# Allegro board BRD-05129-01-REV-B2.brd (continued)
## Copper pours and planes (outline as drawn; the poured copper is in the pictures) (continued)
(no net) on BOTTOM: 102.07,59.7 102.07,56.73 101.77,56.43 98.98,56.43 98.88,56.54 98.88,59.73 99.01,59.86 101.92,59.86
(no net) on BOTTOM: 101.37,83.5 100.63,84.24 100.63,85.06 100.72,85.15 101.02,85.15 101.3,84.87 101.3,84.5 101.8,84 101.8,83.94
(no net) on BOTTOM: 68.31,78.14 65.05,78.14 64.8,77.88 64.8,77.12 64.67,76.99 64.67,75.87 65.33,75.87 65.37,75.87 65.42,75.85 65.94,75.85 66.32,75.47 68.42,75.47 68.55,75.6 68.55,77.9
(no net) on BOTTOM: 26.61,83.81 27.65,83.81 28.62,84.78 28.62,87.42 28.3,87.75 26.48,87.75 26.46,87.72 26.46,83.96
(no net) on BOTTOM: 107.26,34.56 107.26,35.15 108.81,35.15 109.47,34.49 109.47,33.32 109.37,33.21 108.95,33.21 108.8,33.37 108.8,34.08 108.51,34.37 107.46,34.37
(no net) on BOTTOM: 26.66,83.29 27.87,83.29 27.99,83.17 27.99,81.34 27.7,81.05 27.7,79.22 27.48,79.01 26.63,79.01 26.51,78.89 26.51,77.61 26.56,77.56 29.18,77.56 29.45,77.83 29.45,83.53 29.22,83.76 28.01,83.76 27.77,83.52 26.66,83.52
(no net) on BOTTOM: 91.3,86.55 90.82,86.55 90.78,86.51 90.78,83.3 90.85,83.23 91.44,83.23 91.62,83.4 91.62,84.02 91.96,84.36 92.59,84.36 92.79,84.56 92.79,85.01 92.58,85.22 91.43,85.22 91.38,85.28 91.38,86.47
(no net) on BOTTOM: 5.18,54.22 4.97,54.22 4.92,54.17 4.92,52.47 4.72,52.27 4.11,52.27 4.01,52.17 4.01,49.02 6.65,49.02 6.78,49.14 6.78,52.09 6.63,52.24 5.61,52.24 5.25,52.6 5.25,54.15
(no net) on BOTTOM: 123.22,73.57 124.29,73.57 124.75,73.11 126.17,73.11 126.19,73.13 126.19,75.85 125.99,76.06 123.32,76.06 122.82,75.55 122.82,73.97
(no net) on BOTTOM: 123.49,5 129.26,5 130.6,6.35 130.6,17.59 130.1,18.09 125.91,18.09 125.37,17.55 125.37,12.21 122.98,9.83 122.98,5.51
(no net) on BOTTOM: 70.7,38.31 72.33,38.31 72.59,38.06 72.59,36.52 72.47,36.41 70.97,36.41 70.68,36.69 70.68,37.12 70.7,37.17 70.7,37.22
(no net) on BOTTOM: 62.76,77.63 62.76,76.23 62.64,76.11 62.64,73.27 63.87,72.04 66.78,72.04 66.96,72.22 66.96,73.7 66.84,73.82 64.67,73.82 64.42,74.07 64.42,77.63 64.29,77.76 62.89,77.76
(no net) on BOTTOM: 112.21,93.6 112.21,90.25 112.37,90.09 114.53,90.09 114.68,90.24 114.68,91.43 114.43,91.68 113.46,91.68 113.14,92 113.14,93.61 113.04,93.72 112.33,93.72
(no net) on BOTTOM: 36.19,82.19 36.19,81.15 37.15,80.18 39.8,80.18 40.12,80.51 40.12,82.32 40.1,82.35 36.34,82.35
(no net) on BOTTOM: 22.9,86.35 24.3,87.75 25.85,87.75 25.87,87.72 25.87,85.59 25.52,85.23 24.33,85.23 24.2,85.11 24.2,83.66 24.35,83.51 25.65,83.51 25.67,83.48 25.67,83 25.54,82.87 24.4,82.87 24.27,82.74 24.27,80.19 24.64,79.83 25.85,79.83 25.87,79.8 25.87,77.68 25.81,77.62 23.48,77.62 22.9,78.2
(no net) on BOTTOM: 2.82,72.44 4.38,72.44 4.43,72.39 4.43,70.8 4.59,70.64 4.59,69.45 4.4,69.26 2.82,69.26 2.64,69.43 2.64,70.83 2.77,70.95 2.77,72.39
(no net) on BOTTOM: 117.52,5.08 117.52,11.82 116.91,12.43 113.27,12.43 112.11,11.27 112.11,4.57 112.57,4.11 116.56,4.11
(no net) on BOTTOM: 70.91,55.02 72.54,55.02 72.79,54.76 72.79,53.23 72.68,53.11 71.18,53.11 70.89,53.4 70.89,53.82 70.91,53.88 70.91,53.93
(no net) on BOTTOM: 58.71,50.65 58.71,49.43 58.13,48.84 56.59,48.84 56.44,48.99 56.44,50.28 56.81,50.65
(no net) on BOTTOM: 102.07,42.81 102.07,39.84 101.77,39.54 98.98,39.54 98.85,39.67 98.85,42.81 99.01,42.97 101.92,42.97
(no net) on BOTTOM: 18.86,28.69 18.73,28.56 18.73,27.67 19.24,27.04 19.24,26.66 21.02,24.88 27.14,24.88 27.25,24.99 27.25,28.09 26.65,28.69
(no net) on BOTTOM: 58.63,58.8 58.71,58.72 58.71,57.61 58.55,57.44 56.52,57.44 56.38,57.58 56.38,58.57 56.38,58.57 56.51,58.7 57.04,58.7 57.15,58.8
(no net) on BOTTOM: 104.35,70.06 104.64,69.76 104.64,68.56 103.44,67.36 98.22,67.36 98.12,67.45 98.12,69.52 98.66,70.06
(no net) on BOTTOM: 98.85,35.35 98.85,37.77 98.98,37.89 101.14,37.89 101.53,37.5 103.62,37.5 105.15,35.98 105.15,34.78 105.02,34.65 102.4,34.65 101.88,35.16 99.04,35.16
(no net) on BOTTOM: 106.3,51.95 106.87,51.95 106.87,50.36 106.75,50.24 106.35,50.24 106.21,50.39 106.21,51.86
(no net) on BOTTOM: 38.72,85.9 40.12,84.5 40.12,82.96 40.1,82.93 37.96,82.93 37.61,83.29 37.61,84.48 37.48,84.61 36.03,84.61 35.88,84.45 35.88,83.16 35.86,83.13 35.37,83.13 35.25,83.26 35.25,84.4 35.12,84.53 32.57,84.53 32.2,84.17 32.2,82.95 32.18,82.93 30.05,82.93 29.99,82.99 29.99,85.32 30.57,85.9
(no net) on BOTTOM: 106.36,68.85 106.36,67.25 106.24,67.13 105.85,67.13 105.7,67.28 105.7,68.75 105.79,68.85
(no net) on BOTTOM: 74.3,19.39 77.75,19.39 77.95,19.19 77.95,16.98 77.8,16.83 75.68,16.83 75.3,17.21 74.86,17.21 74.78,17.26 74.69,17.28 74.03,17.28 74.03,18.36 74.16,18.48 74.16,19.25
(no net) on BOTTOM: 56.41,64.36 58.42,64.36 58.71,64.06 58.71,63.03 57.18,63.03 57.07,63.14 56.35,63.14 56.3,63.19 56.3,64.25
(no net) on BOTTOM: 101.27,71.42 96.82,71.42 96.57,71.67 96.57,73.71 96.95,74.09 101.57,74.09 101.7,73.96 101.7,71.85
(no net) on BOTTOM: 124.2,17.79 124.2,12.75 122.47,11.02 122.47,5.38 122.09,5 118.54,5 118.03,5.51 118.03,16.35 119.65,17.97 124.02,17.97
(no net) on BOTTOM: 70.9,47.15 72.54,47.15 72.79,46.89 72.79,45.36 72.68,45.24 71.18,45.24 70.89,45.53 70.89,47.14
(no net) on BOTTOM: 56.46,34.77 56.88,34.77 56.96,34.69 56.96,34.62 56.97,34.56 56.99,34.49 56.99,34.45 57.06,34.37 57.08,34.37 57.1,34.37 57.18,34.33 57.26,34.32 58.71,34.32 58.71,33.09 58.56,32.94 56.54,32.94 56.29,33.19 56.29,34.6
(no net) on BOTTOM: 5.56,42.66 5.49,42.59 5.49,40.25 5.36,40.12 4.6,40.12 4.47,40.25 4.47,44.11 4.78,44.42 7.78,44.44 7.9,44.31 9.84,44.31 10.11,44.05 10.11,42.93 9.83,42.66
BRK_CTL_CONN on TOP (solid shape): 117.88,12.04 117.8,11.96 113.1,11.96 113.03,12.04 113.03,12.19 113.15,12.31 113.15,12.87 113.43,13.15 117.88,13.15
BRK_CTL_CONN on TOP (solid shape): 118.31,16.96 118.31,11.55 117.7,10.94 117.7,5.25 116.56,4.11 112.57,4.11 112.11,4.57 112.11,8.3 113.5,8.3 113.5,6 113.5,5.97 113.51,5.91 113.52,5.85 113.54,5.8 113.57,5.74 113.61,5.69 113.65,5.65 113.69,5.6 113.74,5.57 113.8,5.54 113.86,5.52 113.91,5.5 113.98,5.5 114.01,5.5 116.31,5.5 116.34,5.5 116.4,5.5 116.46,5.52 116.52,5.54 116.57,5.57 116.62,5.6 116.67,5.65 116.71,5.69 116.74,5.74 116.77,5.8 116.79,5.85 116.81,5.91 116.81,5.97 116.81,6 116.81,8.3 116.81,8.34 116.81,8.4 116.79,8.46 116.77,8.51 116.74,8.57 116.71,8.62 116.67,8.66 116.62,8.7 116.57,8.74 116.52,8.77 116.46,8.79 116.4,8.8 116.34,8.81 116.31,8.81 114.01,8.81 113.98,8.81 113.91,8.8 113.86,8.79 113.8,8.77 113.74,8.74 113.69,8.7 113.65,8.66 113.61,8.62 113.57,8.57 113.54,8.51 113.52,8.46 113.51,8.4 113.5,8.34 113.5,8.3 112.11,8.3 112.11,11.27 113.05,12.22 117.23,12.22 117.23,12.67 113.15,12.67 113.15,16.86 113.46,17.17 118.11,17.17
BRK_CTL_CONN on BOTTOM (solid shape): 117.52,11.82 117.52,5.08 116.56,4.11 112.57,4.11 112.11,4.57 112.11,8.3 113.5,8.3 113.5,6 113.5,5.97 113.51,5.91 113.52,5.85 113.54,5.8 113.57,5.74 113.61,5.69 113.65,5.65 113.69,5.6 113.74,5.57 113.8,5.54 113.86,5.52 113.91,5.5 113.98,5.5 114.01,5.5 116.31,5.5 116.34,5.5 116.4,5.5 116.46,5.52 116.52,5.54 116.57,5.57 116.62,5.6 116.67,5.65 116.71,5.69 116.74,5.74 116.77,5.8 116.79,5.85 116.81,5.91 116.81,5.97 116.81,6 116.81,8.3 116.81,8.34 116.81,8.4 116.79,8.46 116.77,8.51 116.74,8.57 116.71,8.62 116.67,8.66 116.62,8.7 116.57,8.74 116.52,8.77 116.46,8.79 116.4,8.8 116.34,8.81 116.31,8.81 114.01,8.81 113.98,8.81 113.91,8.8 113.86,8.79 113.8,8.77 113.74,8.74 113.69,8.7 113.65,8.66 113.61,8.62 113.57,8.57 113.54,8.51 113.52,8.46 113.51,8.4 113.5,8.34 113.5,8.3 112.11,8.3 112.11,11.27 113.27,12.43 116.91,12.43
DC_LINK on TOP (solid shape): 110.77,62.28 106.73,62.28 106.73,65.07 108.35,66.7 110.77,66.7
DC_LINK on TOP (solid shape): 111.58,45.23 107.72,45.23 107.72,48.66 108.86,49.81 111.58,49.81
DC_LINK on TOP (solid shape): 112.42,28.37 108.11,28.37 108.11,31.42 107.64,31.42 107.57,31.49 107.57,31.62 108.86,32.91 112.42,32.91
DC_LINK on BOTTOM (solid shape): outline of 103 points within 122.98,5 130.6,18.09
DC_LINK on TOP: outline of 81 points within 93.01,20.75 113.36,66.7
DC_LINK on TOP: 124.51,4.36 128.62,4.36 130.6,6.35 130.6,17.61 130.39,17.83 126.44,17.83 126.44,13.28 123.29,10.13 123.29,5.58
DC_LINK on BOTTOM: 106.47,61.77 99.97,61.77 98.45,60.24 98.45,49.22 99.13,48.54 106.52,48.54 106.52,44.93 102.71,44.93 101.34,43.56 98.9,43.56 98.34,43 98.34,35.17 99.53,33.98 103.24,33.98 104.74,32.48 114.73,32.48 114.73,29 109.77,29 109.52,28.75 109.52,24.81 107.84,23.13 98.62,23.13 96.11,20.62 93.06,20.62 93.01,20.67 93.01,27.35 94.79,29.13 94.79,64.31 95.17,64.69 95.17,65.88 96.14,66.85 106.69,66.85 106.69,61.98
DC_LINK on L03_SIG: 138.48,19.99 138.48,4.36 135.53,1.42 108.99,1.42 108.99,11.24 108.08,12.16 105.98,12.16 104.96,13.17 104.96,14.43 102.89,16.51 88.62,16.51 88.18,16.94 88.18,25.83 90.6,28.24 90.6,64.92 92.4,66.72 104.9,66.72 106.42,65.2 106.42,34.87 107.87,33.42 122.3,33.42 122.3,19.99 ; 1 cut-out
DC_LINK on L07_PWR: 138.73,3.53 136.48,1.28 88.18,1.28 88.18,25.83 90.22,27.86 90.22,64.54 91.11,65.43 138.73,65.43 ; 2 cut-outs
DCLINK_CONN on TOP: 120.39,22.08 120.39,24.71 121.02,25.33 121.02,27.58 122.6,29.16 128.62,29.16 128.98,28.8 128.98,19.14 128.46,18.63 121.89,18.63 121.12,19.4 121.12,21.35
DCLINK_CONN on BOTTOM: 120.39,26.96 122.42,28.98 128.51,28.98 128.98,28.52 128.98,19.14 128.46,18.63 120.83,18.63 120.39,19.07
DCLINK_INPUT on TOP: 118.97,24.86 118.97,22.35 118.89,22.27 118.03,22.27 117.65,21.89 117.65,18.08 117.27,17.7 113.48,17.7 112.7,18.49 112.7,25.6 113.05,25.95 117.9,25.95 118.21,25.65 118.21,25.22 118.31,25.12 118.72,25.12
DCLINK_INPUT on BOTTOM: 113.48,17.7 112.82,18.36 112.82,24.05 119.79,24.05 119.79,18.96 118.53,17.7
DCLINK_VOCM2 on BOTTOM (solid shape): 72.59,38.06 72.59,36.52 72.47,36.41 70.97,36.41 70.68,36.69 70.68,37.12 70.7,37.17 70.7,37.22 70.7,38.31 72.33,38.31
GEM0_AVDD_3V3 on TOP: 68.41,97.92 69.37,97.92 69.39,97.9 69.39,95.72 69.3,95.63 66.92,95.63 66.16,96.38 65.69,96.38 65.66,96.41 65.66,97.15 68.04,97.15 68.12,97.15 68.35,97.38 68.35,97.86
GEM0_AVDD_3V3 on L03_SIG: 69.39,95.68 69.39,96.78 68.97,97.19 65.64,97.19 65.07,96.62 60.24,96.62 59.86,96.24 59.86,95.65 60.93,94.59 67.17,94.59 68.01,95.42 69.13,95.42
GEM1_AVDD_3V3 on BOTTOM: 107.36,90.09 107.36,89.2 107.74,88.82 107.74,87.17 107.36,86.79 106.09,86.79 105.71,87.17 105.71,89.96 105.84,90.09
GEM1_AVDD_3V3 on L10_SIG: 106.6,89.58 106.6,87.02 106.37,86.79 105.69,86.79 105.36,87.12 98.57,87.12 98.12,87.57 93.04,87.57 92.23,88.38 92.23,90.25 92.36,90.38 93.38,90.38 93.48,90.29 93.48,89.56 93.91,89.12 99.48,89.12 100.06,89.7 100.06,90.33 100.28,90.55 100.88,90.55 101.93,89.51 105.23,89.51 105.48,89.76 106.42,89.76
GEM2_AVDD_3V3 on TOP: 107.36,92.98 105.67,92.98 105.44,92.75 105.44,90.36 105.71,90.09 107.36,90.09
GEM2_AVDD_3V3 on L10_SIG: 93.85,89.81 93.85,92.04 94.48,92.68 97.53,92.68 97.96,93.11 106.35,93.11 106.83,92.63 106.83,90.93 106.12,90.22 103.04,90.22 102.18,91.08 99.95,91.08 99.68,90.81 99.68,89.88 99.45,89.66 94,89.66
GISOIN_RS485 on TOP (solid shape): 111.59,80.44 111.59,79.12 111.45,78.98 110.28,78.98 110.05,79.21 110.05,80.31 110.27,80.53 111.51,80.53
GISOIN_RS485 on TOP (solid shape): 115.68,86.78 115.68,85.48 116.83,84.33 116.83,82.65 116.8,82.62 115.05,82.62 114.97,82.69 114.97,84.41 114.35,85.03 114.35,86.87 114.5,87.01 115.44,87.01
GISOIN_RS485 on L05_SIG: 125.32,100.22 127.3,100.22 128.06,99.46 128.06,87.17 123.82,82.93 115.39,82.93 111.5,79.04 109.75,79.04 109.34,79.45 109.34,83.87 113.61,88.13 121.94,88.13 124.08,90.27 124.08,98.98
MOTOR_PA_HS on TOP (solid shape): 114.19,40.88 114.14,40.89 114.09,40.89 114.02,40.89 113.94,40.87 113.94,39.89 114.02,39.88 114.09,39.87 114.14,39.87 114.19,39.88 114.19,37.94 111.07,37.94 111.07,42.19 114.19,42.19
MOTOR_PA_HS on TOP: 114.32,47.32 123.08,47.32 123.08,39.09 122.02,39.09 122.02,37.51 123.08,37.51 123.08,35.5 121.64,34.06 113.94,34.06 113.92,34.03 110.13,34.03 110.13,35.38 109.57,35.94 108.94,35.94 108.71,36.17 108.71,36.77 108.84,36.9 108.84,39.8 108.78,39.85 108.78,41.85 108.94,42.01 113.61,42.01 114.12,42.52 114.12,47.11
MOTOR_PA_HS on L03_SIG: 123.08,35.5 121.64,34.06 113.94,34.06 113.92,34.03 110.13,34.03 110.13,35.38 109.57,35.94 108.94,35.94 108.71,36.17 108.71,36.77 108.84,36.9 108.84,39.8 108.78,39.85 108.78,41.85 108.94,42.01 113.61,42.01 114.12,42.52 114.12,47.11 114.32,47.32 123.08,47.32 ; 1 cut-out
MOTOR_PA_OUT on TOP: 137.93,40.56 137.93,47.67 123.82,47.67 123.82,39.19 126.06,39.19 126.54,39.67 137.04,39.67
MOTOR_PA_OUT on L03_SIG: 137.93,40.56 137.93,47.67 123.82,47.67 123.82,39.19 126.06,39.19 126.54,39.67 137.04,39.67 ; 1 cut-out
MOTOR_PA_VOCM2 on BOTTOM (solid shape): 72.79,46.89 72.79,45.36 72.68,45.24 71.18,45.24 70.89,45.53 70.89,45.95 70.91,46 70.91,46.05 70.91,47.15 72.54,47.15
MOTOR_PB_HS on TOP (solid shape): 114.19,54.83 110.77,54.83 110.77,59 114.19,59
MOTOR_PB_HS on TOP: 123.08,47.93 114.22,47.93 114.07,48.08 114.07,50.52 113.89,50.69 110.16,50.69 110.13,50.72 110.13,52.22 109.67,52.68 108.91,52.68 108.71,52.88 108.71,54.12 108.86,54.28 108.86,59 114.27,59 114.91,58.36 123.08,58.36
MOTOR_PB_HS on L03_SIG: 123.08,47.93 114.22,47.93 114.07,48.08 114.07,50.52 113.89,50.69 110.16,50.69 110.13,50.72 110.13,52.22 109.67,52.68 108.91,52.68 108.71,52.88 108.71,54.12 108.86,54.28 108.86,59 114.27,59 114.91,58.36 123.08,58.36 ; 1 cut-out
MOTOR_PB_OUT on TOP: 137.88,48.33 137.88,54.28 135.86,54.28 135.12,53.54 131.44,53.54 130.7,54.28 124.3,54.28 123.95,53.92 123.95,48.79 124.41,48.33
MOTOR_PB_OUT on L03_SIG: 137.88,48.33 137.88,54.28 135.86,54.28 135.12,53.54 131.44,53.54 130.7,54.28 124.3,54.28 123.95,53.92 123.95,48.79 124.41,48.33 ; 1 cut-out
MOTOR_PB_VOCM2 on BOTTOM (solid shape): 72.79,54.76 72.79,53.23 72.68,53.11 71.18,53.11 70.89,53.4 70.89,53.82 70.91,53.87 70.91,53.93 70.91,55.02 72.54,55.02
MOTOR_PC_HS on TOP (solid shape): 113.69,71.73 110.41,71.73 110.41,75.93 113.69,75.93
MOTOR_PC_HS on TOP, L03_SIG: 107.82,71.37 107.82,69.92 108.15,69.59 109.19,69.59 109.6,69.19 109.6,67.76 109.77,67.59 113.46,67.59 114.09,66.95 114.09,60.63 115.44,59.28 122.78,59.28 123.08,59.58 123.08,65.5 123.06,65.53 123.06,67.15 122.21,68 120.58,68 119.3,69.29 119.3,75.46 118.83,75.93 108.37,75.93 108.37,71.92
MOTOR_PC_OUT on TOP: 124.1,64.03 137.84,64.03 137.84,55.04 135.23,55.04 134.41,54.22 131.8,54.22 130.98,55.04 124.33,55.04 124.1,55.27
MOTOR_PC_OUT on L03_SIG: 124.1,64.03 137.84,64.03 137.84,55.04 135.23,55.04 134.41,54.22 131.8,54.22 130.98,55.04 124.33,55.04 124.1,55.27 ; 1 cut-out
MOTOR_PC_VOCM2 on BOTTOM (solid shape): 72.79,62.19 72.79,60.65 72.68,60.54 71.18,60.54 70.89,60.82 70.89,61.25 70.91,61.3 70.91,61.35 70.91,62.44 72.54,62.44
PA_HB on TOP (solid shape): 101.52,33.83 102.15,33.2 105.2,33.2 105.2,32.48 98.62,32.48 98.62,37.51 101.52,37.51
PA_HO on BOTTOM (solid shape): 106.87,33.47 106.75,33.35 106.35,33.35 106.21,33.5 106.21,34.97 106.3,35.06 106.87,35.06
PA_HOG on BOTTOM (solid shape): 109.47,34.49 109.47,33.32 109.37,33.21 108.95,33.21 108.8,33.37 108.8,34.08 108.51,34.37 107.46,34.37 107.26,34.56 107.26,35.15 108.81,35.15
PA_LO on TOP (solid shape): 106.67,44.55 106.67,43.77 106.61,43.71 105.78,43.71 105.33,43.26 105.33,40.77 105.29,40.7 105.22,40.67 105.2,40.67 104.83,40.31 105.2,39.94 105.35,39.97 105.47,40.05 105.54,40.08 105.61,40.05 105.7,39.97 105.7,38.55 105.28,38.55 105.17,38.67 105.17,39.07 104.24,40 104.24,42.34 104.52,42.62 104.52,43.81 105.36,44.65 106.57,44.65
PA_LOG on TOP (solid shape): 109.57,44.71 109.57,43.29 108.64,43.29 108.26,43.67 107.16,43.67 107.08,43.75 107.08,44.63 107.34,44.88 109.4,44.88
PB_HB on TOP (solid shape): 101.77,54.02 101.77,50.47 101.88,50.36 104.8,50.36 105.03,50.14 105.03,49.2 104.77,48.94 98.88,48.94 98.62,49.2 98.62,49.42 99.27,49.42 99.28,49.37 99.29,49.32 99.31,49.27 99.33,49.22 99.37,49.18 99.4,49.14 99.45,49.11 99.5,49.08 99.55,49.07 99.6,49.06 99.65,49.06 99.71,49.06 99.76,49.08 99.81,49.1 99.85,49.12 99.9,49.16 99.93,49.2 99.96,49.24 99.98,49.29 100,49.34 100.01,49.4 100.01,49.45 100,49.5 99.98,49.56 99.96,49.6 99.93,49.65 99.9,49.69 99.85,49.72 99.81,49.75 99.76,49.77 99.71,49.79 99.65,49.79 99.6,49.79 99.55,49.78 99.5,49.76 99.45,49.74 99.4,49.71 99.37,49.67 99.33,49.63 99.31,49.58 99.29,49.53 99.28,49.48 99.27,49.42 98.62,49.42 98.62,54.4 101.39,54.4
PB_HO on BOTTOM (solid shape): 106.87,50.36 106.75,50.24 106.35,50.24 106.21,50.39 106.21,51.86 106.3,51.95 106.87,51.95
PB_HOG on BOTTOM (solid shape): 109.47,51.38 109.47,50.21 109.37,50.1 108.95,50.1 108.8,50.26 108.8,50.97 108.51,51.26 107.46,51.26 107.26,51.45 107.26,52.04 108.81,52.04
PB_LO on TOP (solid shape): 106.67,60.66 106.61,60.6 105.78,60.6 105.33,60.16 105.33,59.6 105.28,59.59 104.96,59.23 105.28,58.86 105.33,58.86 105.33,57.23 105.7,56.86 105.7,55.44 105.28,55.44 105.17,55.56 105.17,56.47 104.55,57.08 104.55,60.73 105.26,61.44 106.67,61.44
PB_LOG on TOP (solid shape): 109.57,61.61 109.57,60.18 108.64,60.18 108.26,60.56 107.16,60.56 107.08,60.65 107.08,61.52 107.34,61.78 109.4,61.78
PC4_CON_PGND on L10_SIG: 56.77,19.6 56.77,13.51 55.85,12.59 52.6,12.59 48.31,8.3 31.75,8.3 31.09,8.96 31.09,10.54 32.05,11.5 47.06,11.5 50.54,14.98 53.18,14.98 54.15,15.95 54.15,18.69 55.19,19.73 56.64,19.73
PC_HB on TOP (solid shape): 101.07,67.27 101.45,66.9 101.46,66.9 101.47,66.88 101.6,66.79 101.75,66.76 101.91,66.8 102.04,66.9 104.26,66.9 104.38,66.79 104.38,65.98 104.25,65.86 101.88,65.86 101.35,65.32 101.25,65.32 101.18,65.35 101.15,65.43 100.78,65.79 100.42,65.43 100.39,65.35 100.31,65.32 99.79,65.32 99.74,65.33 99.69,65.34 99.65,65.33 99.6,65.32 97.96,65.32 97.44,65.85 97.44,65.88 97.38,66.08 97.23,66.22 97.23,69.67 101.07,69.67
PC_HO on BOTTOM (solid shape): 106.36,67.25 106.24,67.13 105.85,67.13 105.7,67.28 105.7,68.75 105.79,68.85 106.36,68.85
PC_HOG on BOTTOM (solid shape): 108.97,68.27 108.97,67.1 108.86,66.99 108.44,66.99 108.29,67.15 108.29,67.87 108.01,68.15 106.95,68.15 106.75,68.35 106.75,68.93 108.31,68.93
PC_LO on TOP (solid shape): 106.16,78.43 106.16,77.55 106.1,77.5 105.27,77.5 104.82,77.05 104.82,74.12 105.19,73.75 105.19,72.33 104.78,72.33 104.66,72.45 104.66,73.36 104.05,73.97 104.05,77.62 105.03,78.6 105.99,78.6
PC_LOG on TOP (solid shape): 109.06,78.5 109.06,77.07 108.14,77.07 107.75,77.45 106.65,77.45 106.57,77.54 106.57,78.41 106.83,78.67 108.89,78.67
PL_1V8 on BOTTOM (solid shape): 40.12,82.32 40.12,80.51 39.8,80.18 37.15,80.18 36.19,81.15 36.19,82.19 36.34,82.35 40.1,82.35
PL_1V8 on TOP: 12.8,42.34 11.22,42.34 10.38,41.5 10.38,38.1 10.92,37.56 14.65,37.56 21.45,30.77 27.9,30.77 27.91,30.76 40.69,30.76 43.2,33.27 43.2,35.84 45.51,38.15 48.43,38.15 53.64,43.35 53.64,46.66 51.1,49.2 51.1,55.67 50.59,56.18 46.27,56.18 38.65,48.56 38.65,40.56 36.5,38.4 20.7,38.4 18.41,40.69 13.69,40.69 12.85,41.52 12.85,42.29
PL_1V8 on TOP: 69.11,79.95 69.11,76.42 66.29,73.6 61.11,73.6 60.63,74.09 58.19,74.09 57.55,73.45 51.08,73.45 50.57,72.94 33.45,72.94 32.48,73.91 32.48,84.93 33.22,85.67 41.04,85.67 43.99,82.72 52.62,82.72 55.72,79.62 62.05,79.62 62.61,80.18 65.96,80.18 65.96,79.17 66.21,78.91 67.23,78.91 67.61,79.29 67.61,80.18 67.86,80.44 68.63,80.44
PL_1V8 on L03_SIG: 85.98,17.88 85.98,26.21 64.41,47.77 52.22,47.77 50.95,46.5 50.95,43.63 53.36,41.22 55.04,41.22 78.69,17.57 85.67,17.57
PL_1V8 on L07_PWR: 105.05,89.84 105.05,78.96 103.48,77.39 83.28,77.39 64.66,58.77 64.66,41.07 61.85,38.25 39.57,38.25 39.01,38.81 39.01,43.05 39.43,43.47 47,43.47 48.71,45.18 48.71,56.13 51.48,58.9 51.48,69.06 61.54,79.12 61.54,84.3 66.85,84.3 71.01,88.46 71.01,92.32 102.56,92.32
PL_2V5 on BOTTOM (solid shape): 58.71,49.43 58.13,48.84 56.59,48.84 56.44,48.99 56.44,50.28 56.81,50.65 58.71,50.65
PL_2V5 on BOTTOM (solid shape): 58.71,58.72 58.71,57.61 58.55,57.44 56.52,57.44 56.38,57.58 56.38,58.56 56.51,58.7 57.04,58.7 57.15,58.8 58.63,58.8
PL_2V5 on BOTTOM (solid shape): 56.96,34.64 56.96,34.62 56.97,34.56 56.99,34.49 56.99,34.45 57.06,34.37 57.08,34.37 57.1,34.37 57.18,34.33 57.26,34.32 58.71,34.32 58.71,33.09 58.56,32.94 56.54,32.94 56.29,33.19 56.29,34.6 56.46,34.77 56.83,34.77
PL_2V5 on BOTTOM: 58.67,25.73 54.63,25.73 54.28,26.08 54.28,27.99 54.57,28.28 57.29,28.28 57.67,27.9 58.11,27.9 58.19,27.85 58.28,27.83 58.94,27.83 58.94,26.76 58.81,26.63 58.81,25.87
PL_2V5 on BOTTOM: 58.71,42.48 58.71,41.26 58.13,40.68 56.59,40.68 56.44,40.82 56.44,42.11 56.81,42.48
PL_2V5 on L05_SIG: 55.98,59.97 61.51,59.97 61.9,59.58 61.9,25.34 61.67,25.12 56.18,25.12 54.43,26.87 54.43,28.65 55.8,30.02 55.8,59.79
PL_3V3 on BOTTOM (solid shape): 58.71,55.9 58.71,54.88 56.73,54.88 56.28,55.33 56.28,56.53 56.43,56.68 57.93,56.68
PL_3V3 on BOTTOM (solid shape): 58.71,64.06 58.71,63.03 57.18,63.03 57.07,63.14 56.35,63.14 56.3,63.19 56.3,64.25 56.41,64.36 58.42,64.36
PL_3V3 on BOTTOM (solid shape): 74.38,23.97 71.97,23.97 71.42,23.41 70.32,23.41 69.77,23.97 69.76,23.97 69.23,24.5 69.23,25.54 69.38,25.7 74.38,25.7
PL_3V3 on BOTTOM (solid shape): 58.71,39.56 58.71,38.52 57.26,38.52 57.18,38.51 57.11,38.48 57.07,38.46 56.81,38.19 56.41,38.19 56.28,38.32 56.28,39.73 56.44,39.88 58.39,39.88
PL_3V3 on TOP: 107.9,91.58 107.9,93.55 108.12,93.77 109.52,93.77 109.77,93.52 109.77,91.74 109.61,91.58
PL_3V3 on BOTTOM: 62.87,25.74 61.48,25.74 61.22,25.99 61.22,27.83 61.88,27.83 62.04,27.89 62.13,28.03 62.13,28.04 62.24,28.15 62.24,28.53 62.37,28.66 63.38,28.66 63.51,28.53 63.51,26.38
PL_3V3 on BOTTOM: 75.06,84.02 75.44,84.02 75.57,83.89 75.57,82.87 75.44,82.75 73.28,82.75 72.97,83.06 72.97,85.06 73,85.09 74.78,85.09 74.8,85.07 74.8,84.28
PL_3V3 on BOTTOM: 108.38,88.95 109.65,88.95 110.16,88.44 110.16,86.91 110.03,86.79 108.25,86.79 108.25,88.82
PL_3V3 on BOTTOM: 56.43,48.51 57.93,48.51 58.71,47.73 58.71,46.71 56.73,46.71 56.28,47.16 56.28,48.36
PL_3V3 on L03_SIG: 81.12,72.84 84.58,72.84 85.87,71.55 85.87,42.11 83.71,39.95 75.05,39.95 74.37,40.64 74.37,70.91 75.92,72.46 80.74,72.46
PL_3V3 on L07_PWR: 14.42,53.64 15.06,54.28 35.78,54.28 36.62,53.44 36.62,48.48 33.78,45.64 14.63,45.64 14.42,45.84
PL_3V3 on L08_PWR: 73.02,116.45 83.54,116.45 83.54,117.72 86.65,117.72 86.65,117.21 87.25,115.77 88.68,115.18 101.39,115.18 102.83,115.77 103.42,117.21 103.42,117.72 135.05,117.71 137.65,116.63 138.73,114.03 138.73,4.96 137.66,2.36 135.05,1.28 4.95,1.27 2.35,2.35 1.27,4.95 1.27,16 28.32,16 29.03,16.71 29.03,19.02 47.67,19.02 50.77,22.12 50.77,27.66 49.04,29.38 44.29,29.38 40.81,32.86 40.81,43.48 35.94,48.36 35.94,53.41 39.62,57.09 39.62,67.18 42.24,69.79 44.7,69.79 44.73,69.82 45.34,69.82 45.37,69.86 46.49,69.86 49.91,73.27 63.17,73.27 73.02,83.13
PL_4V5_TRQ on TOP (solid shape): 93.48,15.86 93.48,15.01 93.23,14.75 90.1,14.75 89.84,15.01 89.84,15.86 90.1,16.12 93.23,16.12
PL_4V5_TRQ on BOTTOM (solid shape): 77.95,19.19 77.95,16.98 77.8,16.83 77.47,16.83 77.47,17.33 77.39,17.51 77.21,17.58 76.7,17.58 76.6,17.56 76.52,17.5 76.45,17.47 76.38,17.5 76.29,17.56 76.2,17.58 75.69,17.58 75.51,17.51 75.43,17.33 75.43,17.21 74.86,17.21 74.78,17.26 74.69,17.28 74.03,17.28 74.03,18.36 74.16,18.48 74.16,19.25 74.3,19.39 77.75,19.39
PL_4V5_TRQ on L10_SIG: 78.18,4.39 92.6,4.39 93.72,5.51 93.72,15.46 92.63,16.56 87.17,16.56 85.98,15.36 79.04,15.36 77.69,16.71 77.69,19.22 77.44,19.48 71.83,19.48 71.24,18.89 71.24,11.32
PL_5V0 on BOTTOM (solid shape): 126.19,75.85 126.19,73.13 126.17,73.11 124.75,73.11 124.29,73.57 124.09,73.57 124.09,74.04 124.01,74.22 123.83,74.29 123.32,74.29 123.14,74.22 123.07,74.04 123.07,73.96 123.01,73.87 122.9,73.89 122.82,73.97 122.82,75.55 123.32,76.06 125.99,76.06
PL_5V0 on L10_SIG: 136.24,68.98 127.2,68.98 121.54,74.65 121.54,89.76 116.95,94.34 116.95,97.65 117.32,98.01 129.71,98.01 130.86,96.87 130.86,92.17 137.82,85.21 137.82,70.56
PL_12V0 on TOP (solid shape): 105.25,69.83 105.25,69.45 105.2,69.37 105.19,69.29 105.19,67.9 101.99,67.9 101.67,68.23 101.67,70.34 104.74,70.34
PL_12V0 on TOP (solid shape): 105.4,53.31 105.41,53.27 105.4,53.24 105.34,53.13 105.32,53.01 105.43,52.75 105.69,52.64 105.7,52.64 105.74,52.62 105.76,52.59 105.76,52.56 105.75,52.55 105.71,52.48 105.7,52.39 105.7,51.01 102.5,51.01 102.18,51.33 102.18,53.45 105.25,53.45
PL_12V0 on TOP (solid shape): 105.76,36.25 105.76,35.67 105.74,35.65 105.72,35.61 105.7,35.57 105.7,35.53 105.7,35.5 105.7,34.12 102.5,34.12 102.18,34.44 102.18,35.25 102.36,35.43 102.36,35.99 104.83,35.99 104.84,35.93 104.85,35.88 104.87,35.83 104.9,35.78 104.93,35.74 104.97,35.7 105.01,35.67 105.06,35.65 105.11,35.63 105.16,35.62 105.22,35.62 105.27,35.62 105.32,35.64 105.37,35.66 105.42,35.69 105.46,35.72 105.49,35.76 105.52,35.81 105.55,35.86 105.56,35.91 105.57,35.96 105.57,36.01 105.56,36.07 105.55,36.12 105.52,36.17 105.49,36.21 105.46,36.25 105.42,36.29 105.37,36.32 105.32,36.34 105.27,36.35 105.22,36.36 105.16,36.35 105.11,36.34 105.06,36.33 105.01,36.3 104.97,36.27 104.93,36.23 104.9,36.19 104.87,36.14 104.85,36.09 104.84,36.04 104.83,35.99 102.36,35.99 102.36,36.56 105.45,36.56
PL_12V0 on BOTTOM (solid shape): 101.42,54.25 103.77,54.25 105.15,52.87 105.15,51.67 105.02,51.54 102.4,51.54 101.88,52.05 98.88,52.05 98.88,54.55 99.11,54.78 100.88,54.78
PL_12V0 on BOTTOM (solid shape): 104.64,69.76 104.64,68.56 103.44,67.36 102.04,67.36 101.75,67.5 101.46,67.36 98.22,67.36 98.12,67.45 98.12,69.52 98.66,70.06 104.35,70.06
PL_12V0 on BOTTOM (solid shape): outline of 89 points within 98.85,34.65 105.15,37.89
PL_12V0 on BOTTOM: 78.7,25.23 78.7,23.68 77.97,22.95 77.97,21.52 77.99,21.5 80.71,21.5 80.91,21.7 80.91,25.23
PL_12V0 on L08_PWR: 98,28.2 97,27.2 79.68,27.2 78.56,26.08 78.56,20.8 79.63,19.73 105.13,19.73 107.34,21.94 107.34,68.47 106.3,69.52 99.21,69.52 98,68.31
PL_ETH_0V9 on TOP (solid shape): 102.47,83.41 102.44,83.38 101.56,83.38 101.13,83.81 101.13,84.19 100.63,84.69 100.63,85.07 100.82,85.26 101.03,85.26 101.27,85.51 101.27,86.33 101.49,86.55 102.47,86.55
PL_ETH_0V9 on TOP (solid shape): 92.76,84.88 92.76,84.12 92.55,83.92 91.56,83.92 91.49,83.99 91.49,84.08 91.5,84.09 91.54,84.16 91.55,84.25 91.55,84.76 91.55,84.82 91.52,84.87 91.51,84.9 91.6,85 92.12,85 92.16,85 92.2,85.01 92.63,85.01
PL_ETH_0V9 on BOTTOM (solid shape): 101.3,84.87 101.3,84.5 101.77,84.03 101.75,84 101.72,83.94 101.71,83.87 101.71,83.84 101.37,83.5 100.63,84.24 100.63,85.06 100.67,85.1 101.07,85.1
PL_ETH_0V9 on BOTTOM (solid shape): 91.38,86.47 91.38,85.28 91.43,85.22 92.58,85.22 92.79,85.01 92.79,84.56 92.59,84.36 91.96,84.36 91.62,84.02 91.62,83.4 91.44,83.23 90.85,83.23 90.78,83.3 90.78,86.51 90.82,86.55 91.3,86.55
PL_ETH_0V9 on BOTTOM (solid shape): 75.19,91.53 75.19,90.75 74.7,90.75 74.52,90.68 74.44,90.5 74.44,89.99 74.46,89.89 74.52,89.81 74.55,89.73 74.52,89.66 74.46,89.58 74.44,89.48 74.44,88.97 74.52,88.79 74.7,88.72 74.79,88.72 74.88,88.65 74.86,88.54 74.81,88.49 74.81,88.15 74.76,88.07 74.74,87.98 74.74,87.32 73.67,87.32 73.54,87.45 72.97,87.45 72.97,88.47 72.98,88.52 72.98,88.57 72.98,88.61 72.97,88.66 72.97,89.88 73.33,90.24 73.33,90.64 73.35,90.72 73.36,90.8 73.35,90.87 73.33,90.96 73.33,91.23 73.83,91.74 74.98,91.74
PL_ETH_0V9 on L10_SIG: 102.89,86.61 102.89,80.11 99.35,76.56 92.74,76.56 92.55,76.37 79.93,76.37 74.88,81.43 74.88,83.89 74.21,84.55 74.21,86.95 73.73,87.44 73.73,90.22 75.59,92.07 86.15,92.07 91.39,86.84 92.02,86.84 94.31,84.55 98.24,84.55 98.83,85.14 98.83,86.41 99.03,86.61
PMOD_3V3 on L05_SIG: 6.93,17.9 12.87,17.9 13.66,17.12 13.66,8.68 13.2,8.23 8.33,8.23 6.7,9.85 3.12,9.85 2.49,10.49 2.49,16.1 2.99,16.61 5.63,16.61
PS_1V2 on BOTTOM (solid shape): 28.62,87.42 28.62,84.78 27.65,83.81 26.61,83.81 26.46,83.96 26.46,87.72 26.48,87.75 28.3,87.75
PS_1V2 on L12_SIG: 59.89,96.69 65.99,96.69 69.03,93.65 69.03,92.45 67.66,91.08 67.66,87.73 68.79,86.6 68.79,85.76 67.53,84.5 65.86,84.5 65.83,84.53 62.91,84.53 57.1,78.71 51.71,78.71 50.82,77.82 45.56,77.82 44.67,78.71 33.17,78.71 26.97,84.91 26.97,87.37 27.56,87.96 41.58,87.96 46.12,83.41 49.45,83.41 52.4,86.36 56.87,86.36 58.77,88.26 58.77,93.77 59.29,94.29 59.29,96.1
PS_1V8 on TOP (solid shape): 113.93,96.98 113.93,95.58 113.84,95.49 112.83,95.49 112.64,95.67 112.64,96.91 112.88,97.15 113.76,97.15
PS_1V8 on BOTTOM (solid shape): 59.59,78.37 59.59,76.37 59.34,76.12 59.23,76.12 59.23,76.64 59.16,76.82 58.98,76.89 58.47,76.89 58.37,76.87 58.29,76.82 58.21,76.79 58.14,76.82 58.06,76.87 57.96,76.89 57.45,76.89 57.27,76.82 57.2,76.64 57.2,76.57 56.55,76.57 56.5,76.59 56.46,76.59 55.8,76.59 55.8,77.72 55.93,77.84 55.93,78.61 56.18,78.86 59.1,78.86
PS_1V8 on TOP: 42.97,5.08 44.9,5.08 45.06,4.92 45.06,1.62 44.93,1.49 43.33,1.49 42.87,1.95 42.87,4.97
PS_1V8 on BOTTOM: 46.88,1.7 46.88,8.58 44.57,10.89 37.97,10.89 37.16,11.71 37.16,15.57 36.24,16.48 36.24,18.89 34.84,20.29 28.42,20.29 27.99,19.86 27.99,14.65 30.78,11.86 30.78,2.94 32.64,1.09 46.27,1.09
PS_1V8 on L07_PWR: 1.27,81.33 25.52,81.33 29.5,85.3 29.5,94.39 25.57,98.32 1.27,98.32
PS_1V8 on L08_PWR: 44.23,28.63 40.05,32.81 40.05,43.46 35.4,48.1 35.4,53.59 39.09,57.27 39.09,67.51 41.88,70.3 46.27,70.3 49.68,73.71 62.89,73.71 72.54,83.36 72.54,116.45 26.89,116.45 26.89,32.13 29,30.02 29,20.11 28.95,20.06 28.95,19.5 47.47,19.5 50.24,22.27 50.24,27.48 49.08,28.63
PS_1V8 on L10_SIG: 114.47,108.99 113.56,109.9 86,109.9 83.26,107.16 83.26,98.34 88.06,93.54 110.77,93.54 111.04,93.26 111.04,89.33 111.55,88.82 117.65,88.82 118.16,89.33 118.16,91.87 114.47,95.55
PS_1V8 on L12_SIG: 84.91,101.7 84.91,93.85 75.03,83.97 69.67,83.97 69.38,84.26 69.38,86.6 68.07,87.91 68.07,90.83 79.98,102.74 83.87,102.74
PS_1V8_RS485 on TOP (solid shape): 115.49,96.37 115.49,95.51 115.24,95.26 115.24,95.05 114.75,95.05 114.62,95 114.57,94.87 114.57,94.36 114.58,94.31 114.6,94.26 114.6,94.16 114.51,94.11 114.17,94.11 113.94,94.34 113.93,94.36 113.93,95.16 114.35,95.59 114.35,96.37 114.5,96.51 115.35,96.51
PS_1V8_RS485 on L03_SIG: 113.92,94.51 113.92,96.59 115.62,98.29 121.51,98.29 123.8,96.01 123.8,94.33 123.49,94.03 122.45,94.03 122.17,94.31 122.17,94.66 121.76,95.07 115.44,95.07 115.3,94.93 115.3,94.92 114.69,94.31 114.12,94.31
PS_3V3 on BOTTOM (solid shape): 53.51,78.48 53.51,76.59 52.86,76.59 52.73,76.56 52.63,76.46 52.63,76.45 52.5,76.32 52.5,75.94 52.37,75.81 52.07,75.81 52.07,76.34 51.99,76.52 51.82,76.59 51.23,76.59 51.23,78.1 51.86,78.73 53.26,78.73
PS_3V3 on BOTTOM (solid shape): 62.38,77.76 62.38,75.92 61.73,75.92 61.57,75.86 61.48,75.72 61.48,75.71 61.37,75.6 61.37,75.16 60.94,75.16 60.94,75.66 60.87,75.84 60.69,75.92 60.1,75.92 60.1,77.38 60.73,78.01 62.13,78.01
PS_3V3 on BOTTOM (solid shape): 8.05,62.33 8.05,61.39 8.17,61.26 8.46,61.26 8.51,61.25 8.55,61.25 8.79,61.25 8.88,61.16 9,61.13 9.19,61.13 9.32,61.01 9.32,58.97 8.43,58.09 8.43,57.08 7.87,57.08 7.69,57.01 7.62,56.83 7.62,56.23 5.48,56.23 5.41,56.31 5.41,62.43 5.56,62.58 7.79,62.58
PS_3V3 on TOP: 70.97,96.56 69.96,96.56 69.96,98.33 70.41,98.78 71.57,98.78 71.65,98.7 71.65,97.25
PS_3V3 on BOTTOM: 23.87,46.12 29.74,46.12 30.65,47.04 30.65,68.25 30.22,68.68 20.7,68.68 19.99,67.97 19.99,62.3 23.14,59.15 23.14,46.86
PS_3V3 on L10_SIG: 80.49,116.45 82.75,114.19 82.75,99.84 73.35,90.45 73.35,86.99 72.96,86.6 71.19,86.6 70.69,87.1 70.69,89.55 69.87,90.37 68.25,90.37 67.36,89.48 67.36,86.03 67.18,85.85 66.44,85.85 65.91,86.38 60.52,86.38 59.64,87.27 59.64,91.46 58.62,92.48 55.47,92.48 54.33,91.33 54.33,86.89 62.56,78.66 62.56,75.64 62.02,75.1 58.7,75.1 58.09,75.71 58.09,75.74 57.2,76.63 47.24,76.63 45.13,78.74 40.16,78.74 36.1,82.8 29.61,82.8 26.49,79.68 26.49,66.21 23.31,63.04 13.03,63.04 13,63.01 12.37,63.01 12.01,62.66 12.01,60.98 10.03,59 8.99,59 7.45,57.46 1.81,57.46 1.27,58.01 1.27,102.97 10.27,111.97 10.27,117.23 10.74,117.7 59.76,117.7 61.01,116.45
PS_3V3 on L12_SIG: 36.34,28.37 36.34,22.5 34.03,20.19 25.73,20.19 20.8,25.12 20.8,43.4 25.35,47.95 28.32,47.95 29.03,47.24 29.03,30.17 30.58,28.62 32,28.62 32.58,29.21 35.51,29.21
PS_ETH_0V9 on BOTTOM (solid shape): 68.55,77.9 68.55,75.6 68.42,75.47 68.1,75.47 68.1,75.96 68.03,76.14 67.85,76.22 67.34,76.22 67.24,76.2 67.16,76.14 67.08,76.11 67.01,76.14 66.93,76.2 66.83,76.22 66.32,76.22 66.14,76.14 66.07,75.96 66.07,75.85 65.5,75.85 65.42,75.9 65.33,75.92 64.67,75.92 64.67,76.99 64.8,77.12 64.8,77.88 65.05,78.14 68.31,78.14
PS_ETH_0V9 on L07_PWR: 57.96,94.26 68.58,94.26 70.51,92.32 70.51,88.62 66.72,84.83 51.38,84.83 50.14,86.08 50.14,94.18 50.86,94.91 57.3,94.91
PS_ETH_0V9 on L10_SIG: 70.28,89.53 70.28,76.68 69.59,75.99 65.73,75.99 64.18,77.54 64.18,78.46 62.28,80.36 60.96,80.36 52.24,89.07 52.24,90.37 52.82,90.94 54.54,90.94 55.57,91.97 58.42,91.97 59.1,91.28 59.1,87.07 60.22,85.95 65.71,85.95 66.29,85.37 67.28,85.37 67.74,85.82 67.74,89.23 68.5,89.99 69.82,89.99
SDIO_VDD on TOP: 31.91,115.69 31.17,115.69 31.15,115.67 31.15,113.36 30.76,112.97 30.76,110.3 30.95,110.12 32.06,110.12 32.18,110.24 32.18,112.89 31.92,113.15 31.92,115.67
SDIO_VDD on L03_SIG: 34.92,97.71 36.83,97.71 37.79,98.67 37.79,111.55 36.09,113.25 30.98,113.25 30.76,113.03 30.76,110.38 31.19,109.95 31.64,109.95 32.3,109.29 32.3,107.31 35.91,103.7 35.91,99.61 34.79,98.5 34.79,97.84
SOM_5V0 on BOTTOM (solid shape): 6.59,79.85 6.59,76.88 6.49,76.79 4.77,76.79 4.77,78.24 4.72,78.39 4.6,78.51 4.6,79.84 4.76,80 6.43,80
SOM_5V0 on L03_SIG: 18.74,78.56 18.74,82.52 17.88,83.38 7.9,83.38 4.49,79.98 4.49,75.41 5.36,74.54 10.89,74.54 11.38,75.03 11.38,77.54 11.68,77.85 18.03,77.85
USB0_VBUS2 on BOTTOM: 39.67,97.91 40.08,97.91 40.23,98.07 40.23,99.56 40.1,99.69 39.62,99.69 39.54,99.61 39.54,98.04
USB0_VBUS2 on L05_SIG: 47.54,96.95 47.54,96.44 46.83,95.73 42.06,95.73 39.29,98.5 39.29,100.58 40.18,101.47 44.83,101.47 46.25,102.89 46.25,103.81 47.37,104.92 52.02,104.92 54.15,107.06 57.86,107.06 59.25,105.66 59.25,101.52 58.49,100.76 54.15,100.76 54.14,100.74 53.78,100.74 51.39,98.36 48.95,98.36
USB0_VBUS3 on BOTTOM: 38.88,97.94 38.35,97.94 38.27,98.01 38.27,99.46 38.53,99.72 38.93,99.72 39.09,99.56 39.09,98.14
USB0_VBUS3 on L10_SIG: 37.79,99.72 37.79,97.91 40.36,95.35 50.47,95.35 54.76,99.64 59.05,99.64 59.91,100.5 59.91,107.16 58.97,108.1 51.91,108.1 51.51,107.69 51.51,101.85 50.14,100.48 38.55,100.48
USB_JTAG_FLTR on TOP (solid shape): 53.51,9.57 53.51,8.43 53.31,8.23 52.45,8.23 52.45,8.72 52.4,8.85 52.27,8.9 51.76,8.9 51.63,8.85 51.58,8.72 51.58,8.23 51.43,8.23 51.43,8.72 51.38,8.85 51.25,8.9 50.74,8.9 50.62,8.85 50.57,8.72 50.57,8.23 50.19,8.23 50.19,9.16 50.85,9.83 53.26,9.83
USB_JTAG_FLTR on BOTTOM (solid shape): 45,16.09 45,11.9 44.72,11.62 42.97,11.62 42.97,13.3 42.84,13.42 42.84,14.31 43.86,14.31 43.99,14.44 43.99,15.46 43.86,15.58 42.84,15.58 42.84,16.34 42.97,16.47 44.62,16.47
USB_JTAG_FLTR on L05_SIG: 44.9,16.96 45.21,16.66 45.21,10.69 46.05,9.85 53.41,9.85 53.79,9.47 53.79,7.72 53.41,7.34 43.89,7.34 42.62,8.61 42.62,16.35 43.23,16.96
USB_JTAG_VBUS on TOP (solid shape): 55.55,9.19 55.55,8.84 55.47,8.75 55.45,8.64 55.45,8.2 55.42,8.17 54.66,8.17 54.4,7.92 54.4,7.41 54.15,7.16 54.15,5.89 53.89,5.63 53.89,3.48 53.51,3.48 53.51,4 53.57,4.16 53.59,4.33 53.59,4.53 53.57,4.71 53.51,4.87 53.51,5.63 52.62,6.52 52.62,7.67 53.64,7.67 53.77,7.79 53.77,8.56 54.53,9.32 55.42,9.32
USB_JTAG_VCORE on L03_SIG: 53.16,25.57 61.62,25.57 63.17,24.02 63.17,21.46 62.78,21.08 60.75,21.08 58.8,23.03 53.39,23.03 52.98,23.44 52.98,25.4
USB_JTAG_VCORE on L10_SIG: 63.67,23.34 66.98,20.04 66.98,13.03 63.75,9.8 53.11,9.8 52.42,10.49 52.42,11.48 53.06,12.11 58.01,12.11 60.12,14.22 63.45,14.22 64.31,15.08 64.31,19.1 63.45,19.96 61.69,19.96 61.26,20.39 61.26,22.68 61.92,23.34
USB_JTAG_VPHY on TOP (solid shape): 57.7,18.08 57.7,16.3 57.6,16.2 57.57,16.22 57.53,16.23 57.49,16.23 56.99,16.23 56.87,16.18 56.82,16.06 56.82,15.55 56.87,15.42 56.99,15.37 57.5,15.37 57.5,14.76 57.96,14.3 57.96,13.57 57.69,13.31 56.72,13.31 56.29,13.74 56.26,13.77 56.13,13.9 56.13,18.03 56.3,18.21 57.58,18.21
USB_JTAG_VPLL on TOP: 49.02,12.4 50.76,12.4 50.97,12.18 50.97,10.46 50.47,9.95 49.29,9.95 49.29,10.65 49.02,10.92
USB_JTAG_VPLL on L03_SIG: 55.19,10.81 55.19,9.39 54.43,8.63 49.63,8.63 49.27,8.99 49.27,10.66 50.16,11.55 51.61,11.55 51.8,11.37 54.63,11.37
USB_PWRD_VCCIO on TOP (solid shape): 59.74,19.6 59.74,16.56 58.34,16.56 58.34,19.48 58.59,19.73 59.61,19.73
USB_PWRD_VCCIO on TOP (solid shape): 48.43,10.97 47.92,10.97 47.29,10.33 46.66,10.33 46.53,10.46 46.53,11.98 46.78,12.24 48.43,12.24
USB_PWRD_VCCIO on BOTTOM: 40.69,14.31 40.69,13.63 39.97,12.92 39.97,11.87 39.6,11.49 37.88,11.49 37.69,11.68 37.69,12.92 38.47,12.92 38.65,13.1 38.65,14.69 38.78,14.82 39.54,14.82 39.8,14.57 39.8,14.44 39.92,14.31
USB_PWRD_VCCIO on L12_SIG: 69.13,16.28 69.13,22.12 59.53,31.72 56.36,31.72 49.45,38.63 41.47,38.63 40.15,37.31 30.73,37.31 29.94,36.52 29.94,29.99 30.88,29.05 31.77,29.05 32.3,29.59 35.58,29.59 37.46,27.71 37.46,13.13 40.29,10.3 45.68,10.3 46.02,9.95 62.81,9.95
UTIL_3V3 on BOTTOM (solid shape): 10.19,42.05 10.19,39.51 10.01,39.34 8.14,39.34 8.14,39.84 8.12,39.94 8.07,40.03 8.04,40.1 8.07,40.17 8.12,40.25 8.14,40.35 8.14,40.86 8.07,41.04 7.89,41.11 7.32,41.11 7.32,41.51 7.4,41.6 7.44,41.73 7.44,42.25 7.44,42.26 9.98,42.26
UTIL_3V3 on L05_SIG: 10.36,41.88 10.36,39.39 4.64,33.68 4.64,17.29 4.36,17.01 1.72,17.01 1.27,17.47 1.27,37.74 5.66,42.13 10.11,42.13
VISOIN_RS485 on TOP (solid shape): 113.66,79.82 113.66,79.05 113.36,78.75 112.41,78.75 112.23,78.93 112.23,79.99 113.49,79.99
VISOIN_RS485 on TOP (solid shape): 118.13,86.27 118.13,82.67 118.1,82.64 117.45,82.64 117.33,82.76 117.33,84.48 116.69,85.12 116.69,86.59 116.95,86.85 117.54,86.85
VISOIN_RS485 on L03_SIG: 117.52,87.02 116.33,87.02 112.06,82.75 112.06,78.81 112.24,78.63 113.76,78.63 114.3,79.17 114.3,81.58 117.75,85.03 117.75,86.79
VISOOUT_RS485 on TOP (solid shape): 113.1,84.35 113.1,82.64 113.44,82.3 113.83,82.3 113.91,82.22 113.91,80.67 113.64,80.39 112.28,80.39 112.23,80.45 112.23,84.32 112.34,84.43 113.03,84.43
VISOOUT_RS485 on BOTTOM (solid shape): 113.1,84.04 113.1,82.63 113.45,82.28 113.74,82.28 113.84,82.18 113.84,80.66 113.73,80.55 112.53,80.55 112.35,80.73 112.35,84.1 112.39,84.14 112.99,84.14
VREF_DCLINK on TOP (solid shape): 64.63,37.74 64.75,37.67 64.88,37.65 64.93,37.65 65.44,37.15 65.44,35.75 64.94,35.25 63.92,35.25 63.92,37.74
VREF_PA on TOP (solid shape): 64.59,45.95 64.72,45.85 64.88,45.82 64.95,45.82 65.4,45.37 65.4,43.77 65.02,43.39 64.76,43.39 64.66,43.29 64.04,43.29 63.92,43.42 63.92,45.91 63.96,45.95
VREF_PB on TOP (solid shape): 64.59,54.12 64.64,54.07 64.71,54.03 64.97,53.77 65.1,53.77 65.39,53.48 65.39,51.92 65,51.52 64.88,51.52 64.77,51.51 64.67,51.46 64.04,51.46 63.92,51.59 63.92,54.08 63.96,54.12
VREF_PC on TOP (solid shape): 64.59,62.29 64.72,62.19 64.88,62.15 64.91,62.15 65.41,61.65 65.41,60.01 65.19,59.79 65.12,59.74 65.08,59.69 64.88,59.69 64.77,59.67 64.67,59.63 64.04,59.63 63.92,59.75 63.92,62.24 63.96,62.29
N16074248 on TOP: 29.03,21.51 30.55,21.51 30.83,21.79 30.83,24.3 30.53,24.61 29.41,24.61 29.38,24.58 29.38,22.93 29,22.55 29,21.53
N16189579 on TOP (solid shape): 102.07,42.81 102.07,39.82 98.62,39.82 98.62,42.71 98.88,42.97 101.92,42.97
N16189579 on BOTTOM (solid shape): 102.07,42.81 102.07,39.84 101.77,39.54 98.98,39.54 98.85,39.67 98.85,42.81 99.01,42.97 101.92,42.97
N16189629 on TOP (solid shape): 102.07,59.7 102.07,56.71 98.62,56.71 98.62,59.61 98.88,59.86 101.92,59.86
N16189629 on BOTTOM (solid shape): 102.07,59.7 102.07,56.73 101.77,56.43 98.98,56.43 98.88,56.54 98.88,59.73 99.01,59.86 101.92,59.86
N16189705 on TOP (solid shape): 101.7,73.99 101.7,72.36 101.16,71.83 96.9,71.83 96.57,72.16 96.57,73.91 96.74,74.09 101.6,74.09
N16189705 on BOTTOM (solid shape): 101.7,73.96 101.7,71.85 101.27,71.42 96.82,71.42 96.57,71.67 96.57,73.71 96.95,74.09 101.57,74.09
N17444223 on BOTTOM: 39.59,18.37 39.59,16.72 36.75,16.72 36.75,18.37
N17444428 on BOTTOM: 46.66,18.46 46.66,16.94 43.73,16.94 43.73,18.46

Small or netless copper shapes (teardrops, artwork), in the pictures only: 5 on TOP

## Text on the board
BOTTOM: 14 | LAYER 14 BOTTOM | UL94V0 | 128-05129-01 REV B2
Board Geometry/Soldermask Bottom: 18 | SOLDERMASK BOTTOM
Package Geometry/Pastemask Bottom: 20 | PASTEMASK BOTTOM
Ref Des/Silkscreen Bottom: A | 12V_IN | PS_3V3 | PS_1V2 | PS_1V8 | PL_2V5 | PS_ETH_0V9 | PL_3V3 | PL_1V8 | PL_4V5_TRQ | PL_12V0 | MOTOR PB V | PL_5V0 | MOTOR PC V | UTIL_3V3 | 12V_IN_JACK | 5V0_IN | PL_ETH_0V9 | MOTOR PA V | PN 128-05129-01 REV B2 | 16 | SILKSCREEN BOTTOM | RoHS
User.Comments: CR_CLKCHIP_1 | CR_SOMMODULES_1 | CR_U19_1 | CR_HUB43_1 | CR_PS_3V3_REG_1 | CR_8PIN_1 | CR_IC2CHIP_1 | CR_LED_10 | CR_LED_9 | CR_PSETH2V5_1 | CR_PSETH1V0_1 | CR_INA260_ADDRR_1 | CR_TPS_SUPPLY-B_2 | CR_TPS_SUPPLY-B_1 | CR_ETHPWR2_1 | CR_ETHPWR1_1 | CR_WD_1 | CR_DCCNTRL_1 | MH3 | J1 | R51 | TP3 | C52 | MH4 | SW2 | SW1 | Q5 | R50 | R46 | C50 | U41 | C207 | U18 | TP1 | C204 | J15 | R168 | Q22 | C239 | R269 | 11 | 12 | TP23 | J6 | C74 | J2 | C128 | C258 | C338 | C251 | C330 | C334 | C341 | C335 | C337 | C333 | R138 | R137 | C252 | TP19 | 17 | J8 | U15 | 34 | 18 | 15 | J7 | U9 | C23 | A1 | C43 | U34 | TP24 | U7 | C22 | C42 | C127 | DS1 | DS6 | DS2 | DS3 | DS4 | DS5 | C267 | TP7 | 1 | 2 | R205 | X4 | C41 | R194 | R186 | R178 | R188 | R185 | R187 | R189 | R192 | R193 | R180 | C62 | C69 | J5 | C107 | R176 | J3 | U32 | U17 | C240 | C242 | C247 | C343 | C332 | C260 | C331 | C342 | C244 | R81 | R146 | R141 | R145 | C245 | R151 | C246 | C214 | C213 | C254 | L4 | MH7 | D | X3 | C | MH5 | C80 | R66 | 4 | L5 | C88 | C87 | 5 | R179 | R190 | R181 | R89 | 19 | C81 | U11 | B | 40 | 20 | 60 | C78 | R241 | U31 | C101 | C326 | A | JA1 | 8 | C79 | C325 | X7 | C49 | U19 | U24 | X8 | U46 | C103 | C82 | C85 | R75 | U44 | X5 | C277 | C275 | C316 | R221 | R222 | C315 | C309 | C310 | L3 | C83 | C84 | L2 | X2 | X6 | R15 | U10 | R10 | TP13 | 14 | 13 | 7 | C13 | C146 | C145 | C173 | C172 | R103 | R113 | R114 | R115 | C158 | U38 | U36 | C197 | C202 | C200 | C199 | C198 | R108 | R107 | R106 | R102 | R125 | R104 | R105 | R109 | R116 | TP17 | 6 | J17 | Q4 | Q3 | Q2 | R112 | C16 | MH2 | U12 | C17 | J16 | JA2 | MH1 | MH8 | MH6 | D1 | U16 | U61 | U62 | J4 | U68 | U43 | U67 | J11 | J10 | J12 | C203 | Q21 | TP5 | R265 | C235 | C234 | TP9 | R135 | R133 | C206 | C205 | J13 | C117 | C118 | C119 | C120 | C121 | C122 | TP29 | TP27 | TP28 | C123 | C124 | TP30 | C340 | TP32 | TP33 | TP34 | TP31 | C241 | R206 | C268 | C248 | C215 | C106 | C255 | R38 | C249 | C21 | R199 | R80 | R171 | R23 | C211 | R24 | R85 | C112 | C63 | R173 | R39 | R172 | C216 | R170 | C111 | R83 | R73 | C110 | C227 | C70 | C60 | C226 | C58 | C212 | C59 | C229 | U28 | U30 | U27 | C57 | R174 | C228 | C54 | R169 | C231 | C61 | R155 | C72 | C55 | C67 | C56 | TP37 | U55 | C230 | U58 | C233 | U49 | C232 | C90 | U52 | C89 | R182 | R177 | C91 | R40 | TP38 | C92 | R41 | TP39 | C93 | C44 | R36 | C95 | C301 | C99 | C102 | C305 | C276 | R262 | C302 | C100 | C306 | C97 | R217 | R74 | R216 | R78 | R219 | C105 | R76 | R220 | R77 | U26 | TP21 | TP15 | C104 | C94 | TP11 | C279 | C281 | C280 | C282 | C12 | C15 | C349 | C351 | C347 | U40 | C195 | C345 | TP35 | C190 | TP36 | R240 | C194 | R6 | C164 | C192 | C14 | R17 | C193 | C189 | C350 | C346 | R127 | R124 | C352 | C348 | U50 | U51 | PCB EDGE | RESET | FWUEN | PS_SRST_L | MIO26 | IAS_2V75 | GND | PL_1V2 | PS | PL | IAS 0 | IAS 1 | PWR IN | SOM LPD | SOM FPD | CC PS | SOM PL | CC PL | PL_1V8 | UTIL_3V3 | USB 3/4 | USB 1/2 | ETH_2V5 | WATCHDOG OUT | 12VIN | 5V0_IN | PS_1V2 | 12V-IN-JACK | SCK | SDA | SOM240_1 | PL_3V3 | PS_1V8 | PS_3V3 | CONTACT | RASPBERRY PI | SOM240_2 | ETH_1V0 | J9
TOP: 1 | TOP SIDE
Board Geometry/Soldermask Top: 17 | SOLDERMASK TOP
Package Geometry/Pastemask Top: 19 | PASTEMASK TOP
Ref Des/Silkscreen Top: DIFF ENCODER INPUT | PS_3V3 | UTIL_3V3 | SOM LPD | CC PL | SOM PL | UF1 | PWR IN | SOM FPD | CC PS | UF2 | PS_1V2 | GND | MIO26 | PS_1V8 | A | PL_2V5 | PL_3V3 | SENSE | PL_12V0 | PL_1V8 | DIFF | SE | PL_4V5 | MOTOR PC GD | SNS_P | SNS_N | BRAKE | DCLINK A | CANH | CANL | DC_LINK | RS485 AB TERM | PL_5V0 | MOTOR ON | EN | DIS | Z | B | Y | MOTOR PC C | MOTOR PA C | MOTOR PB C | 12V_IN | 12V_IN_JACK | 5V0_IN | D | C | JTAG/UART | PS_ETH_0V9 | TEMP SENSOR | PL_ETH_0V9 | PL_4V5_TRQ | PL GEM1 TOP | PL GEM2 BOT | TORQUE SENSOR | ENCODER SEL | MOTOR PA GD | MOTOR PB GD | BRAKE CONN | CAN TERM | MOTOR PA | MOTOR PB | MOTOR PC | DCLINK V | SE ENCODER INPUT | MOTOR CONNECTOR | FAN HDR | JTAG MODE | PMU RESET EN | DC LINK | RESET | FWUEN | PMOD | 12V PWR | SOM240_1 | SD 2.0 | JTAG | SOM40 | USB | PS GEM0 | CAN 2.0 | RS485 | 15 | SILKSCREEN TOP
L02_GND: 2 | LAYER 2 GROUND
L03_SIG: 3 | LAYER 3 SIGNAL
L04_GND: 4 | LAYER 4 GROUND
L05_SIG: 5 | LAYER 5 SIGNAL
L06_GND: 6 | LAYER 6 GROUND
L07_PWR: 7 | LAYER 7 POWER
L08_PWR: 8 | LAYER 8 POWER
L09_GND: 9 | LAYER 9 GROUND
L10_SIG: 10 | LAYER 10 SIGNAL
L11_GND: 11 | LAYER 11 GROUND
L12_SIG: 12 | LAYER 12 SIGNAL
L13_GND: 13 | LAYER 13 GROUND
XSECTION_CHART: *  SURFACE - AIR 0 MIL(+0/-0) | *  DIELECTRIC - CONFORMAL_COAT 0.8 MIL(+0/-0) | L1 TOP CONDUCTOR - 05OZ_CU+PLATING 1.9 MIL(+0/-0) | *  DIELECTRIC - P001-EM-828G-1080X1-RC66-PREG-3P21 3.1 MIL(+0/-0) | L2 L02_GND PLANE - 05OZ_CU 0.6 MIL(+0/-0) | *  DIELECTRIC - C001-EM-828G-2113X1-RC54-CORE-4P0 4 MIL(+0/-0) | L3 L03_SIG CONDUCTOR - 05OZ_CU 0.6 MIL(+0/-0) | *  DIELECTRIC - P002-EM-828G-2116X1-RC56-PREG-4P77 4.8 MIL(+0/-0) | L4 L04_GND PLANE - 05OZ_CU 0.6 MIL(+0/-0) | L5 L05_SIG CONDUCTOR - 05OZ_CU 0.6 MIL(+0/-0) | L6 L06_GND PLANE - 05OZ_CU 0.6 MIL(+0/-0) | *  DIELECTRIC - C002-EM-828G-1067X1-RC68P8-CORE-2P5 2.5 MIL(+0/-0) | L7 L07_PWR PLANE - 1OZ_CU 1.2 MIL(+0/-0) | *  DIELECTRIC - P003-EM-828G-2113X1-RC59-PREG-3P84 3.7 MIL(+0/-0) | L8 L08_PWR PLANE - 1OZ_CU 1.2 MIL(+0/-0) | L9 L09_GND PLANE - 05OZ_CU 0.6 MIL(+0/-0) | *  DIELECTRIC - P002-EM-828G-2116X1-RC56-PREG-4P77 4.9 MIL(+0/-0) | L10 L10_SIG CONDUCTOR - 05OZ_CU 0.6 MIL(+0/-0) | L11 L11_GND PLANE - 05OZ_CU 0.6 MIL(+0/-0) | L12 L12_SIG CONDUCTOR - 05OZ_CU 0.6 MIL(+0/-0) | L13 L13_GND PLANE - 05OZ_CU 0.6 MIL(+0/-0) | L14 BOTTOM CONDUCTOR - 05OZ_CU+PLATING 1.9 MIL(+0/-0) | DESIGN CROSS SECTION CHART | ___________________________ | TOTAL THICKNESS 64 MIL | 1-14 | 1-3 | 12-14 | STACKUP TABLE | Unit = Mils | # | 1 | 2 | 3 | 4 | 5 | 6 | 7 | 8 | 9 | 10 | 11 | 12 | 13 | 14 | NAME | TOP | L02_GND | L03_SIG | L04_GND | L05_SIG | L06_GND | L07_PWR | L08_PWR | L09_GND | L10_SIG | L11_GND | L12_SIG | L13_GND | BOTTOM | TYPE | SURFACE | DIELECTRIC | CONDUCTOR | PLANE | MATERIAL | AIR | CONFORMAL_COAT | 05OZ_CU+PLATING | P001-EM-828G-1080X1-RC66-PREG-3P21 | 05OZ_CU | C001-EM-828G-2113X1-RC54-CORE-4P0 | P002-EM-828G-2116X1-RC56-PREG-4P77 | C002-EM-828G-1067X1-RC68P8-CORE-2P5 | 1OZ_CU | P003-EM-828G-2113X1-RC59-PREG-3P84 | TOTAL THICKNESS | THICKNESS | 0 | 0.8 | 1.9 | 3.1 | 0.6 | 4.8 | 2.5 | 1.2 | 3.7 | 4.9 | 64
PAGE_OUTLINE: Reflow Process Direction | 4x ∅2.03 Solder Mask | 4x ∅3.20 %%P 0.05 Tooling Hole | 4x ∅1.03 Fiducial Mark | C | ISSUED | CHECKED | ENGRG | DRAWN | 2023 | ADVANCED MICRO DEVICES | REV | DATE | APPROVED | 05/11/2023 | 04/04/2023 | CGN/GI | JIN WU & RYAN HANSEN | UNLESS OTHERWISE SPECIFIED | SCALE | SIZE | FSCM NO | DWG NO | NONE | ANGLES : +/- 5.0 | SIGNATURES | DESCRIPTION | SAN JOSE, CA 95124 | 2100 LOGIC DR. | REVISIONS | B2 | D
DIMENSION: slot:40x118(mils) | 40 | 118 | 2x slot: 32x59(mils) | slot: 138x40(mils) | slot: 118x40(mils) | 59 | 138 | 32 | 2x slot: 26x33(mils) | 33 | 26 | 2x slot: 67x24(mils) | 67 | 24 | ARTWORK, ROHS COMPLIANT, SC-KD240-05129-01 | PCB #    128-05129-01  REV B2 | Designed by AMD | SHEET     OF 20 | LAYER: | CGN/GI | DATE: | PHONE:879-4451 | AMD DOC USE ONLY | REVISION: B2 | DATAPACK: aa | 05/11/2023 | .790 | .560 | 4xR.195 | 4.291 | .050 | .100 | 2XR.030 | LINEAR DIMENSIONS +/-.005 | DIMENSIONS ARE IN INCHES
DISPLAY_TOP: R | E115289 | Electrical Safety | U168 | US | C | N | I | Z | E | D | A | 1 | 60 | 40 | 20 | O | G | JA1 | JA2 | 10 | MET | RoHS | D3C386 | HF
BODY_CENTER: SOM240 | SOM40 | FAN HEADER | 12V | LEDs | 12V DC | JACK | HEADER | PMOD | JTAG | SD2.0 | JTAG/UART | FTDI | USB CON | TEMP SENSOR | CONNECTOR | PS GEM0 | PL GEM1 | TORQUE | SENSOR | CAN 2.0 | BRAKE | RS485 | ENCODER INPUT | SINGLE ENDED | DIFFERENTIAL | MOTOR | DC LINK POWER
